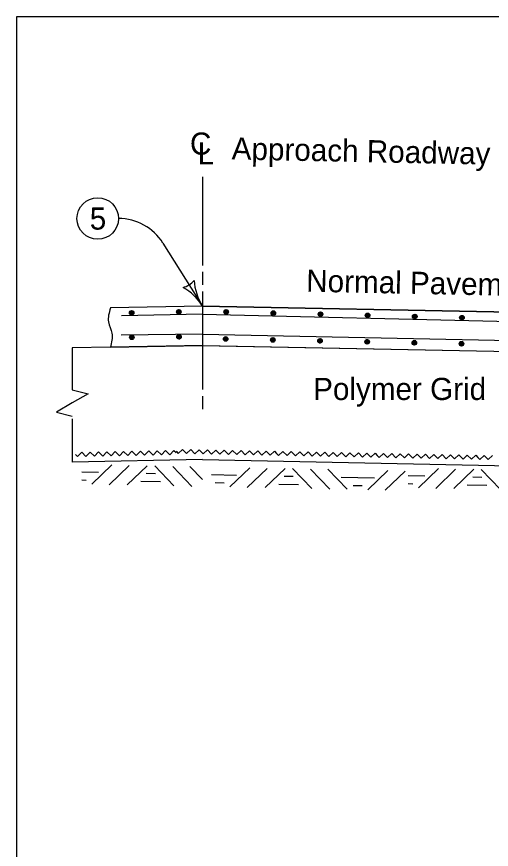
# Model space of a CAD drawing. Extents: x 5546 to 81668, y 3174 to 15999.
# Drawn here: x 17333 to 17675, y 9343 to 9944 of the extents above; entities that cross this region are included whole.
import ezdxf

# ---------------------------------------------------------------- set-up
doc = ezdxf.new("R2010")
doc.units = 0
for name, color, linetype in [('Level 61', 7, 'Continuous'), ('PS_BOLT', 7, 'Continuous'), ('PS_CONST', 7, 'Continuous'), ('PS_DIM', 7, 'Continuous'), ('PS_TEXT', 7, 'Continuous')]:
    doc.layers.add(name, color=color, linetype=linetype)

msp = doc.modelspace()

# ---------------------------------------------------------------- linework, layer by layer
at = {"layer": 'Level 61'}
msp.add_lwpolyline([(17332.52, 9944.02), (20467.53, 9944.02), (20467.53, 7924.02), (17332.52, 7924.02)], close=True, dxfattribs=at)
at = {"layer": 'PS_BOLT'}
msp.add_line((18198.1, 9699.22), (17466.58, 9714.38), dxfattribs=at)
at = {"layer": 'PS_CONST'}
msp.add_line((17438.06, 9780.48), (17466.63, 9734.93), dxfattribs=at)
for centre, radius, start, end in [((17406.03, 9760.39), 37.81, 32.09002, 90), ((17448.73, 9763.47), 15.52, 284.35693, 319.82363), ((17500.66, 9756.27), 40.18, 184.01779, 212.09028), ((17432.59, 9713.59), 40.18, 32.09028, 60.16277)]:
    msp.add_arc(centre, radius, start, end, dxfattribs=at)
at = {"layer": 'PS_DIM'}
for p, q in [((17466.62, 9734.93), (17400.24, 9733.6)), ((17466.62, 9734.93), (17400.24, 9733.6)), ((18176.88, 9720.67), (17466.62, 9734.93)), ((17466.62, 9734.93), (18176.88, 9720.67)), ((17466.59, 9729.18), (17408.07, 9727.87)), ((17466.59, 9729.18), (18198.18, 9711.52)), ((17466.59, 9714.61), (17408.06, 9713.99)), ((17400.24, 9705.23), (17372.68, 9704.68)), ((17372.68, 9704.68), (17372.68, 9674.42)), ((17467.19, 9706.58), (17400.24, 9705.23)), ((17400.24, 9705.23), (17466.05, 9706.55)), ((17466.05, 9706.58), (17466.62, 9706.56)), ((17466.05, 9706.58), (18215.16, 9691.54)), ((17466.62, 9706.56), (17467.19, 9706.58)), ((17467.19, 9706.55), (18215.16, 9691.54)), ((17372.68, 9674.42), (17384.03, 9671.58)), ((17384.03, 9671.58), (17372.68, 9664.97)), ((17372.68, 9664.97), (17361.34, 9658.35)), ((17361.34, 9658.35), (17372.68, 9655.51)), ((17372.68, 9653.51), (17372.68, 9622.26)), ((17466.62, 9624.14), (17372.68, 9622.26)), ((17466.62, 9624.14), (18283.21, 9607.75)), ((17401.31, 9620.19), (17386.88, 9606.34)), ((17413.75, 9619.72), (17399.33, 9605.86)), ((17426.76, 9619.68), (17412.34, 9605.83)), ((17432.17, 9619.58), (17446.03, 9605.15)), ((17445.17, 9619.09), (17459.03, 9604.67)), ((17457.62, 9619.06), (17466.72, 9609.59)), ((17500.84, 9618.2), (17486.42, 9604.34)), ((17513.28, 9617.72), (17498.86, 9603.87)), ((17526.29, 9617.69), (17511.87, 9603.83)), ((17531.7, 9617.58), (17545.56, 9603.15)), ((17544.7, 9617.09), (17558.56, 9602.67)), ((17557.16, 9617.07), (17571.01, 9602.64)), ((17600.37, 9616.2), (17585.95, 9602.34)), ((17612.81, 9615.72), (17598.39, 9601.87)), ((17636.91, 9617.56), (17622.49, 9603.7)), ((17649.35, 9617.08), (17634.93, 9603.23)), ((17662.36, 9617.05), (17647.94, 9603.19)), ((17667.77, 9616.94), (17681.63, 9602.52))]:
    msp.add_line(p, q, dxfattribs=at)
for points in [[(17466.62, 9828.35), (17466.62, 9764.39)], [(17466.63, 9759.66), (17466.63, 9750.21)], [(17466.62, 9745.48), (17466.62, 9674.58)], [(17451.05, 9730.7), (17450.77, 9731.25), (17450.47, 9732.11), (17449.58, 9732.23), (17448.81, 9732.08), (17448.12, 9731.5), (17448.23, 9730.67), (17448.39, 9729.81), (17449.1, 9729.42), (17449.83, 9729.37), (17450.77, 9729.93), (17450.82, 9730.57), (17450.57, 9731.43), (17449.98, 9732.11), (17449.16, 9732.06), (17448.51, 9731.48), (17448.48, 9730.69), (17448.68, 9729.83), (17449.17, 9729.72), (17449.77, 9729.56), (17450.47, 9730.01), (17450.43, 9730.64), (17450.28, 9731.36), (17449.85, 9731.86), (17449.14, 9731.57), (17448.74, 9731), (17448.75, 9730.27), (17449.15, 9730.11), (17449.6, 9729.89), (17450.16, 9730.28), (17450.27, 9730.82), (17449.99, 9731.29), (17449.45, 9731.3), (17449.08, 9731.03), (17448.97, 9730.53), (17449.18, 9730.3), (17449.48, 9730.18), (17449.91, 9730.45), (17449.97, 9730.8), (17449.76, 9731.13), (17449.47, 9731.06), (17449.29, 9730.8), (17449.32, 9730.46), (17449.56, 9730.47), (17449.68, 9730.78)], [(17482.2, 9730.67), (17482.47, 9731.22), (17482.78, 9732.07), (17483.67, 9732.2), (17484.44, 9732.04), (17485.12, 9731.46), (17485.01, 9730.64), (17484.85, 9729.77), (17484.14, 9729.39), (17483.4, 9729.34), (17482.47, 9729.9), (17482.42, 9730.53), (17482.68, 9731.4), (17483.26, 9732.08), (17484.09, 9732.02), (17484.73, 9731.44), (17484.77, 9730.65), (17484.56, 9729.8), (17484.07, 9729.68), (17483.47, 9729.53), (17482.77, 9729.97), (17482.82, 9730.61), (17482.97, 9731.32), (17483.4, 9731.83), (17484.11, 9731.54), (17484.5, 9730.97), (17484.5, 9730.24), (17484.09, 9730.07), (17483.64, 9729.86), (17483.09, 9730.24), (17482.98, 9730.79), (17483.26, 9731.25), (17483.79, 9731.27), (17484.16, 9731), (17484.27, 9730.5), (17484.06, 9730.27), (17483.76, 9730.15), (17483.34, 9730.42), (17483.27, 9730.77), (17483.49, 9731.09), (17483.77, 9731.02), (17483.95, 9730.76), (17483.92, 9730.43), (17483.69, 9730.44), (17483.56, 9730.75)], [(17417.02, 9729.94), (17416.74, 9730.49), (17416.44, 9731.34), (17415.55, 9731.48), (17414.78, 9731.33), (17414.09, 9730.74), (17414.2, 9729.92), (17414.36, 9729.05), (17415.07, 9728.66), (17415.8, 9728.62), (17416.74, 9729.17), (17416.79, 9729.81), (17416.53, 9730.67), (17415.95, 9731.36), (17415.12, 9731.3), (17414.48, 9730.72), (17414.45, 9729.94), (17414.65, 9729.07), (17415.14, 9728.96), (17415.74, 9728.81), (17416.44, 9729.25), (17416.4, 9729.88), (17416.25, 9730.6), (17415.82, 9731.11), (17415.11, 9730.81), (17414.71, 9730.25), (17414.72, 9729.51), (17415.12, 9729.35), (17415.57, 9729.14), (17416.13, 9729.52), (17416.23, 9730.06), (17415.96, 9730.53), (17415.42, 9730.54), (17415.05, 9730.27), (17414.94, 9729.77), (17415.15, 9729.55), (17415.45, 9729.42), (17415.87, 9729.69), (17415.94, 9730.04), (17415.73, 9730.37), (17415.44, 9730.3), (17415.26, 9730.04), (17415.29, 9729.7), (17415.53, 9729.72), (17415.65, 9730.02)], [(17516.23, 9729.85), (17516.5, 9730.4), (17516.81, 9731.25), (17517.69, 9731.38), (17518.47, 9731.23), (17519.15, 9730.64), (17519.05, 9729.82), (17518.88, 9728.95), (17518.17, 9728.56), (17517.43, 9728.52), (17516.5, 9729.08), (17516.45, 9729.72), (17516.71, 9730.57), (17517.3, 9731.26), (17518.12, 9731.2), (17518.76, 9730.62), (17518.8, 9729.84), (17518.59, 9728.97), (17518.1, 9728.86), (17517.5, 9728.71), (17516.8, 9729.15), (17516.85, 9729.78), (17517, 9730.5), (17517.43, 9731.01), (17518.14, 9730.71), (17518.53, 9730.15), (17518.53, 9729.41), (17518.12, 9729.25), (17517.67, 9729.04), (17517.12, 9729.42), (17517, 9729.97), (17517.29, 9730.43), (17517.82, 9730.44), (17518.19, 9730.17), (17518.3, 9729.68), (17518.09, 9729.45), (17517.79, 9729.32), (17517.37, 9729.6), (17517.3, 9729.95), (17517.52, 9730.27), (17517.8, 9730.2), (17517.98, 9729.94), (17517.95, 9729.61), (17517.71, 9729.62), (17517.59, 9729.92)], [(17550.26, 9729.03), (17550.53, 9729.57), (17550.84, 9730.43), (17551.72, 9730.56), (17552.5, 9730.4), (17553.18, 9729.82), (17553.07, 9728.99), (17552.91, 9728.13), (17552.2, 9727.74), (17551.46, 9727.7), (17550.53, 9728.25), (17550.48, 9728.89), (17550.74, 9729.75), (17551.32, 9730.44), (17552.15, 9730.38), (17552.79, 9729.8), (17552.83, 9729.01), (17552.62, 9728.15), (17552.13, 9728.04), (17551.53, 9727.89), (17550.83, 9728.33), (17550.88, 9728.96), (17551.03, 9729.68), (17551.45, 9730.19), (17552.17, 9729.89), (17552.56, 9729.32), (17552.56, 9728.59), (17552.15, 9728.43), (17551.7, 9728.22), (17551.14, 9728.6), (17551.03, 9729.14), (17551.32, 9729.61), (17551.85, 9729.62), (17552.22, 9729.35), (17552.33, 9728.85), (17552.12, 9728.63), (17551.82, 9728.5), (17551.4, 9728.78), (17551.32, 9729.12), (17551.55, 9729.45), (17551.83, 9729.38), (17552.01, 9729.12), (17551.98, 9728.78), (17551.74, 9728.8), (17551.62, 9729.1)], [(17584.28, 9728.2), (17584.56, 9728.75), (17584.87, 9729.61), (17585.75, 9729.74), (17586.52, 9729.58), (17587.21, 9728.99), (17587.1, 9728.17), (17586.94, 9727.31), (17586.23, 9726.92), (17585.49, 9726.88), (17584.56, 9727.43), (17584.51, 9728.07), (17584.77, 9728.93), (17585.36, 9729.62), (17586.18, 9729.56), (17586.82, 9728.97), (17586.86, 9728.19), (17586.65, 9727.33), (17586.15, 9727.22), (17585.56, 9727.07), (17584.86, 9727.51), (17584.91, 9728.14), (17585.06, 9728.86), (17585.48, 9729.37), (17586.2, 9729.07), (17586.59, 9728.51), (17586.59, 9727.77), (17586.18, 9727.61), (17585.73, 9727.4), (17585.17, 9727.78), (17585.06, 9728.33), (17585.35, 9728.79), (17585.88, 9728.8), (17586.25, 9728.53), (17586.36, 9728.03), (17586.15, 9727.81), (17585.85, 9727.68), (17585.43, 9727.95), (17585.35, 9728.3), (17585.58, 9728.63), (17585.86, 9728.56), (17586.04, 9728.3), (17586.01, 9727.96), (17585.77, 9727.98), (17585.65, 9728.28)], [(17618.31, 9727.38), (17618.59, 9727.93), (17618.9, 9728.79), (17619.78, 9728.91), (17620.56, 9728.76), (17621.24, 9728.18), (17621.14, 9727.35), (17620.97, 9726.49), (17620.26, 9726.1), (17619.53, 9726.05), (17618.59, 9726.61), (17618.54, 9727.25), (17618.8, 9728.11), (17619.39, 9728.8), (17620.21, 9728.74), (17620.85, 9728.15), (17620.89, 9727.37), (17620.68, 9726.51), (17620.18, 9726.4), (17619.59, 9726.25), (17618.89, 9726.69), (17618.94, 9727.32), (17619.09, 9728.04), (17619.51, 9728.55), (17620.23, 9728.25), (17620.62, 9727.68), (17620.62, 9726.95), (17620.21, 9726.79), (17619.76, 9726.57), (17619.2, 9726.96), (17619.09, 9727.5), (17619.38, 9727.97), (17619.91, 9727.98), (17620.28, 9727.71), (17620.39, 9727.21), (17620.18, 9726.98), (17619.88, 9726.86), (17619.46, 9727.13), (17619.39, 9727.48), (17619.61, 9727.81), (17619.89, 9727.74), (17620.07, 9727.48), (17620.04, 9727.14), (17619.8, 9727.16), (17619.68, 9727.46)], [(17652.34, 9726.56), (17652.62, 9727.11), (17652.92, 9727.96), (17653.81, 9728.1), (17654.58, 9727.94), (17655.27, 9727.35), (17655.16, 9726.53), (17655, 9725.67), (17654.29, 9725.28), (17653.56, 9725.24), (17652.62, 9725.79), (17652.57, 9726.43), (17652.83, 9727.29), (17653.42, 9727.98), (17654.24, 9727.92), (17654.88, 9727.33), (17654.92, 9726.55), (17654.71, 9725.69), (17654.21, 9725.57), (17653.62, 9725.43), (17652.92, 9725.87), (17652.96, 9726.5), (17653.12, 9727.22), (17653.54, 9727.72), (17654.26, 9727.43), (17654.65, 9726.86), (17654.65, 9726.13), (17654.24, 9725.97), (17653.79, 9725.75), (17653.23, 9726.14), (17653.13, 9726.68), (17653.41, 9727.15), (17653.94, 9727.16), (17654.31, 9726.89), (17654.42, 9726.39), (17654.21, 9726.16), (17653.91, 9726.04), (17653.49, 9726.31), (17653.42, 9726.66), (17653.64, 9726.98), (17653.93, 9726.92), (17654.1, 9726.66), (17654.07, 9726.32), (17653.83, 9726.34), (17653.71, 9726.64)], [(17451.18, 9712.69), (17450.91, 9713.25), (17450.62, 9714.11), (17449.73, 9714.25), (17448.96, 9714.11), (17448.27, 9713.52), (17448.36, 9712.7), (17448.51, 9711.84), (17449.21, 9711.44), (17449.95, 9711.38), (17450.89, 9711.92), (17450.95, 9712.56), (17450.71, 9713.43), (17450.13, 9714.12), (17449.3, 9714.08), (17448.65, 9713.5), (17448.61, 9712.72), (17448.8, 9711.85), (17449.3, 9711.73), (17449.89, 9711.57), (17450.6, 9712.01), (17450.56, 9712.64), (17450.42, 9713.36), (17450, 9713.87), (17449.28, 9713.59), (17448.88, 9713.03), (17448.87, 9712.29), (17449.27, 9712.12), (17449.72, 9711.91), (17450.29, 9712.28), (17450.4, 9712.82), (17450.13, 9713.3), (17449.59, 9713.31), (17449.22, 9713.05), (17449.1, 9712.55), (17449.31, 9712.32), (17449.61, 9712.19), (17450.03, 9712.46), (17450.11, 9712.81), (17449.89, 9713.14), (17449.6, 9713.07), (17449.42, 9712.81), (17449.45, 9712.48), (17449.69, 9712.49), (17449.82, 9712.79)], [(17417.14, 9712.33), (17416.87, 9712.88), (17416.58, 9713.74), (17415.69, 9713.88), (17414.92, 9713.74), (17414.23, 9713.16), (17414.32, 9712.34), (17414.47, 9711.47), (17415.18, 9711.07), (17415.91, 9711.02), (17416.86, 9711.57), (17416.91, 9712.2), (17416.67, 9713.06), (17416.09, 9713.76), (17415.26, 9713.71), (17414.61, 9713.14), (17414.57, 9712.35), (17414.76, 9711.49), (17415.26, 9711.37), (17415.85, 9711.21), (17416.56, 9711.64), (17416.52, 9712.28), (17416.38, 9713), (17415.96, 9713.51), (17415.25, 9713.22), (17414.84, 9712.66), (17414.84, 9711.93), (17415.23, 9711.76), (17415.69, 9711.54), (17416.25, 9711.92), (17416.36, 9712.46), (17416.09, 9712.93), (17415.56, 9712.95), (17415.18, 9712.68), (17415.06, 9712.19), (17415.27, 9711.95), (17415.57, 9711.83), (17415.99, 9712.1), (17416.07, 9712.44), (17415.85, 9712.77), (17415.57, 9712.7), (17415.39, 9712.45), (17415.41, 9712.11), (17415.65, 9712.13), (17415.78, 9712.42)], [(17484.91, 9711.07), (17484.66, 9711.62), (17484.39, 9712.49), (17483.51, 9712.66), (17482.74, 9712.54), (17482.02, 9711.99), (17482.1, 9711.16), (17482.22, 9710.28), (17482.91, 9709.87), (17483.64, 9709.79), (17484.6, 9710.3), (17484.68, 9710.94), (17484.46, 9711.81), (17483.9, 9712.52), (17483.08, 9712.5), (17482.41, 9711.95), (17482.34, 9711.16), (17482.51, 9710.3), (17483, 9710.16), (17483.59, 9709.98), (17484.31, 9710.39), (17484.29, 9711.03), (17484.17, 9711.75), (17483.77, 9712.28), (17483.04, 9712.01), (17482.62, 9711.47), (17482.59, 9710.73), (17482.99, 9710.55), (17483.43, 9710.32), (17484.01, 9710.68), (17484.14, 9711.22), (17483.88, 9711.7), (17483.34, 9711.73), (17482.96, 9711.48), (17482.83, 9710.98), (17483.03, 9710.74), (17483.33, 9710.61), (17483.76, 9710.86), (17483.84, 9711.21), (17483.64, 9711.54), (17483.35, 9711.49), (17483.16, 9711.24), (17483.17, 9710.9), (17483.42, 9710.9), (17483.55, 9711.2)], [(17518.95, 9710.38), (17518.69, 9710.94), (17518.42, 9711.8), (17517.54, 9711.98), (17516.77, 9711.86), (17516.05, 9711.3), (17516.13, 9710.48), (17516.25, 9709.6), (17516.94, 9709.18), (17517.68, 9709.11), (17518.63, 9709.62), (17518.71, 9710.26), (17518.49, 9711.13), (17517.94, 9711.84), (17517.11, 9711.82), (17516.44, 9711.26), (17516.37, 9710.48), (17516.54, 9709.61), (17517.03, 9709.48), (17517.62, 9709.3), (17518.34, 9709.71), (17518.32, 9710.34), (17518.2, 9711.07), (17517.8, 9711.6), (17517.08, 9711.33), (17516.65, 9710.78), (17516.63, 9710.05), (17517.02, 9709.87), (17517.47, 9709.64), (17518.04, 9709.99), (17518.17, 9710.53), (17517.91, 9711.01), (17517.38, 9711.05), (17517, 9710.79), (17516.86, 9710.3), (17517.06, 9710.07), (17517.36, 9709.92), (17517.79, 9710.18), (17517.88, 9710.53), (17517.68, 9710.86), (17517.38, 9710.8), (17517.2, 9710.56), (17517.2, 9710.21), (17517.45, 9710.22), (17517.59, 9710.52)], [(17552.98, 9709.7), (17552.72, 9710.26), (17552.45, 9711.13), (17551.57, 9711.29), (17550.8, 9711.17), (17550.09, 9710.62), (17550.16, 9709.79), (17550.28, 9708.92), (17550.98, 9708.5), (17551.71, 9708.43), (17552.66, 9708.94), (17552.75, 9709.57), (17552.53, 9710.45), (17551.97, 9711.16), (17551.14, 9711.13), (17550.47, 9710.58), (17550.4, 9709.8), (17550.57, 9708.93), (17551.07, 9708.8), (17551.66, 9708.62), (17552.37, 9709.03), (17552.35, 9709.66), (17552.23, 9710.39), (17551.83, 9710.91), (17551.11, 9710.65), (17550.68, 9710.1), (17550.66, 9709.37), (17551.05, 9709.18), (17551.5, 9708.95), (17552.07, 9709.31), (17552.2, 9709.85), (17551.95, 9710.33), (17551.41, 9710.36), (17551.03, 9710.11), (17550.89, 9709.62), (17551.09, 9709.38), (17551.39, 9709.24), (17551.82, 9709.5), (17551.91, 9709.84), (17551.71, 9710.18), (17551.42, 9710.12), (17551.23, 9709.87), (17551.24, 9709.53), (17551.48, 9709.53), (17551.62, 9709.83)], [(17587.01, 9709.01), (17586.76, 9709.57), (17586.49, 9710.44), (17585.61, 9710.61), (17584.84, 9710.49), (17584.12, 9709.93), (17584.19, 9709.11), (17584.31, 9708.23), (17585.01, 9707.82), (17585.74, 9707.74), (17586.7, 9708.26), (17586.78, 9708.89), (17586.56, 9709.76), (17586, 9710.48), (17585.18, 9710.45), (17584.51, 9709.89), (17584.44, 9709.12), (17584.6, 9708.24), (17585.1, 9708.11), (17585.69, 9707.94), (17586.41, 9708.35), (17586.39, 9708.97), (17586.27, 9709.7), (17585.86, 9710.23), (17585.14, 9709.96), (17584.72, 9709.41), (17584.69, 9708.68), (17585.09, 9708.5), (17585.53, 9708.27), (17586.11, 9708.63), (17586.23, 9709.17), (17585.98, 9709.65), (17585.44, 9709.68), (17585.06, 9709.43), (17584.93, 9708.93), (17585.13, 9708.7), (17585.43, 9708.56), (17585.86, 9708.82), (17585.94, 9709.16), (17585.74, 9709.49), (17585.45, 9709.44), (17585.26, 9709.19), (17585.27, 9708.85), (17585.52, 9708.85), (17585.65, 9709.15)], [(17621.04, 9708.33), (17620.79, 9708.89), (17620.52, 9709.76), (17619.64, 9709.93), (17618.87, 9709.81), (17618.15, 9709.25), (17618.23, 9708.43), (17618.35, 9707.56), (17619.04, 9707.14), (17619.77, 9707.06), (17620.73, 9707.57), (17620.81, 9708.21), (17620.59, 9709.08), (17620.03, 9709.79), (17619.21, 9709.77), (17618.54, 9709.21), (17618.47, 9708.43), (17618.64, 9707.56), (17619.13, 9707.43), (17619.72, 9707.25), (17620.44, 9707.66), (17620.42, 9708.29), (17620.3, 9709.02), (17619.9, 9709.54), (17619.18, 9709.28), (17618.75, 9708.74), (17618.73, 9708), (17619.12, 9707.82), (17619.56, 9707.59), (17620.14, 9707.94), (17620.27, 9708.48), (17620.01, 9708.97), (17619.47, 9709), (17619.09, 9708.74), (17618.96, 9708.25), (17619.16, 9708.01), (17619.46, 9707.88), (17619.89, 9708.13), (17619.97, 9708.47), (17619.77, 9708.81), (17619.48, 9708.75), (17619.29, 9708.5), (17619.3, 9708.16), (17619.55, 9708.17), (17619.68, 9708.47)], [(17655.08, 9707.64), (17654.83, 9708.21), (17654.56, 9709.07), (17653.67, 9709.24), (17652.9, 9709.12), (17652.18, 9708.57), (17652.26, 9707.74), (17652.38, 9706.87), (17653.07, 9706.45), (17653.81, 9706.37), (17654.76, 9706.89), (17654.84, 9707.53), (17654.62, 9708.4), (17654.07, 9709.11), (17653.24, 9709.09), (17652.58, 9708.53), (17652.5, 9707.75), (17652.67, 9706.87), (17653.16, 9706.75), (17653.75, 9706.57), (17654.47, 9706.98), (17654.45, 9707.61), (17654.34, 9708.34), (17653.93, 9708.86), (17653.21, 9708.6), (17652.79, 9708.05), (17652.76, 9707.32), (17653.15, 9707.14), (17653.6, 9706.91), (17654.17, 9707.26), (17654.3, 9707.8), (17654.04, 9708.28), (17653.51, 9708.31), (17653.13, 9708.06), (17652.99, 9707.57), (17653.19, 9707.33), (17653.49, 9707.19), (17653.92, 9707.45), (17654.01, 9707.79), (17653.81, 9708.13), (17653.51, 9708.07), (17653.33, 9707.82), (17653.34, 9707.48), (17653.58, 9707.49), (17653.72, 9707.79)], [(17466.05, 9706.55), (17466.05, 9706.58)], [(17467.19, 9706.58), (17467.19, 9706.55)], [(17466.62, 9669.86), (17466.62, 9660.41)], [(17374.95, 9627.74), (17376.49, 9626.25), (17379.45, 9629.34), (17382.54, 9626.38), (17385.5, 9629.46), (17388.59, 9626.5), (17391.55, 9629.58), (17394.63, 9626.62), (17397.6, 9629.7), (17400.68, 9626.74), (17403.65, 9629.82), (17406.73, 9626.86), (17409.7, 9629.95), (17412.78, 9626.99), (17415.74, 9630.07), (17418.83, 9627.11), (17421.79, 9630.19), (17424.88, 9627.22), (17427.84, 9630.31), (17430.93, 9627.35), (17433.89, 9630.43), (17436.98, 9627.47), (17439.94, 9630.56), (17443.03, 9627.59), (17445.99, 9630.68), (17447.53, 9629.19)], [(17447.53, 9630.05), (17449.01, 9628.51), (17452.1, 9631.47), (17455.06, 9628.39), (17458.15, 9631.35), (17461.11, 9628.26), (17464.19, 9631.23), (17467.16, 9628.14), (17470.24, 9631.11), (17473.21, 9628.02), (17476.29, 9630.99), (17479.26, 9627.9), (17482.34, 9630.86), (17485.3, 9627.78), (17488.39, 9630.74), (17491.35, 9627.66), (17494.44, 9630.62), (17497.4, 9627.54), (17500.49, 9630.5), (17503.45, 9627.42), (17506.54, 9630.38), (17509.5, 9627.29), (17512.59, 9630.26), (17515.55, 9627.17), (17518.64, 9630.14), (17520.12, 9628.59)], [(17520.12, 9628.59), (17521.6, 9627.05), (17524.68, 9630.01), (17527.65, 9626.93), (17530.73, 9629.89), (17533.69, 9626.81), (17536.78, 9629.77), (17539.74, 9626.69), (17542.83, 9629.65), (17545.79, 9626.57), (17548.88, 9629.53), (17551.84, 9626.44), (17554.93, 9629.41), (17557.89, 9626.32), (17560.97, 9629.29), (17563.94, 9626.2), (17567.02, 9629.17), (17569.99, 9626.08), (17573.07, 9629.04), (17576.04, 9625.96), (17579.12, 9628.92), (17582.09, 9625.84), (17585.17, 9628.8), (17588.13, 9625.72), (17591.22, 9628.68), (17592.7, 9627.14)], [(17592.7, 9627.14), (17594.18, 9625.6), (17597.27, 9628.56), (17600.23, 9625.47), (17603.32, 9628.43), (17606.28, 9625.35), (17609.37, 9628.32), (17612.33, 9625.23), (17615.41, 9628.2), (17618.38, 9625.11), (17621.46, 9628.07), (17624.43, 9624.99), (17627.51, 9627.95), (17630.48, 9624.86), (17633.56, 9627.83), (17636.52, 9624.74), (17639.61, 9627.71), (17642.57, 9624.63), (17645.66, 9627.59), (17648.62, 9624.5), (17651.71, 9627.46), (17654.67, 9624.38), (17657.76, 9627.34), (17660.72, 9624.26), (17663.8, 9627.22), (17665.29, 9625.68)], [(17665.29, 9625.68), (17666.77, 9624.14), (17669.85, 9627.1), (17672.82, 9624.02), (17675.9, 9626.98)], [(17379.59, 9615.15), (17391.62, 9614.91)], [(17426.09, 9614.2), (17432.62, 9614.07)], [(17473.09, 9613.28), (17491.15, 9612.92)], [(17525.62, 9612.2), (17532.15, 9612.07)], [(17615.19, 9612.52), (17627.22, 9612.28)], [(17379.47, 9609.36), (17382.74, 9609.29)], [(17422.14, 9608.42), (17436.33, 9608.14)], [(17475.74, 9607.42), (17482.27, 9607.29)], [(17521.67, 9606.42), (17535.86, 9606.14)], [(17566.63, 9611.4), (17590.68, 9610.92)], [(17615.07, 9606.72), (17618.34, 9606.65)], [(17657.74, 9605.78), (17671.93, 9605.5)], [(17661.69, 9611.56), (17668.22, 9611.43)], [(17575.27, 9605.43), (17581.8, 9605.3)]]:
    msp.add_lwpolyline(points, dxfattribs=at)
for centre in [(17449.53, 9730.76), (17483.72, 9730.73), (17415.5, 9730), (17517.75, 9729.91), (17551.78, 9729.09), (17585.81, 9728.26), (17619.84, 9727.44), (17653.87, 9726.62), (17415.62, 9712.41), (17449.66, 9712.77), (17483.39, 9711.19), (17517.43, 9710.51), (17551.46, 9709.82), (17585.49, 9709.14), (17619.52, 9708.46), (17653.56, 9707.77)]:
    msp.add_circle(centre, 1.65, dxfattribs=at)
msp.add_spline([(17400.24, 9733.6), (17398.73, 9723.51), (17401.19, 9715.39), (17400.24, 9705.23)], degree=3, dxfattribs=at)
msp.add_spline([(17400.24, 9733.6), (17398.73, 9723.51), (17401.19, 9715.39), (17400.24, 9705.23)], degree=3, dxfattribs=at)
at = {"layer": 'PS_TEXT'}
msp.add_circle((17391.03, 9798.2), 15, dxfattribs=at)

# ---------------------------------------------------------------- texts
at = {"layer": 'PS_CONST'}
for s, p in [('C', (17457.6, 9844.33)), ('L', (17463.14, 9837.26)), ('Polymer Grid', (17546.5, 9667.11))]:
    msp.add_text(s, height=16, dxfattribs=at).set_placement(p)
for s, p in [('Approach Roadway', (17487.58, 9840.87)), ('Normal Pavement Slope', (17541.38, 9745.36))]:
    msp.add_text(s, height=16, rotation=358.85018, dxfattribs=at).set_placement(p)
at = {"layer": 'PS_TEXT'}
msp.add_text('5', height=16, dxfattribs=at).set_placement((17385.26, 9790.2))

doc.saveas('drawing.dxf')
